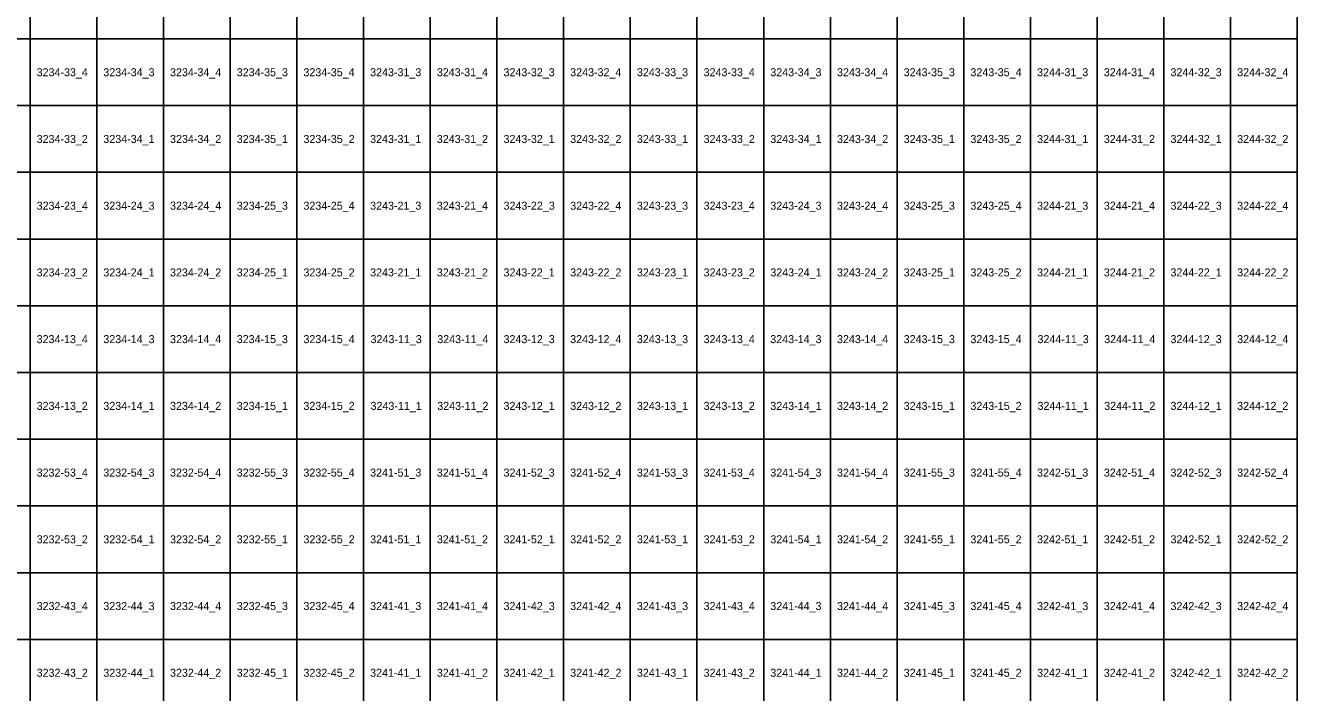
# Model space of a CAD drawing. Extents: x 312500 to 765000, y 172500 to 440000.
# Drawn here: x 437325 to 484827, y 265505 to 290507 of the extents above; entities that cross this region are included whole.
import ezdxf

# ---------------------------------------------------------------- set-up
doc = ezdxf.new("R2010")
doc.units = 0
doc.layers.add('Topo5_ramis_TKS2025', color=7, linetype='Continuous')
doc.layers.add('Topo5_ramis_TKS2025_Nr', color=7, linetype='Continuous')

msp = doc.modelspace()

# ---------------------------------------------------------------- linework, layer by layer
at = {"layer": 'Topo5_ramis_TKS2025'}
for points in [[(435000, 290000), (435000, 292500), (437500, 292500), (437500, 290000), (435000, 290000)], [(437500, 290000), (437500, 292500), (440000, 292500), (440000, 290000), (437500, 290000)], [(440000, 290000), (440000, 292500), (442500, 292500), (442500, 290000), (440000, 290000)], [(442500, 290000), (442500, 292500), (445000, 292500), (445000, 290000), (442500, 290000)], [(445000, 290000), (445000, 292500), (447500, 292500), (447500, 290000), (445000, 290000)], [(447500, 290000), (447500, 292500), (450000, 292500), (450000, 290000), (447500, 290000)], [(450000, 290000), (450000, 292500), (452500, 292500), (452500, 290000), (450000, 290000)], [(452500, 290000), (452500, 292500), (455000, 292500), (455000, 290000), (452500, 290000)], [(455000, 290000), (455000, 292500), (457500, 292500), (457500, 290000), (455000, 290000)], [(457500, 290000), (457500, 292500), (460000, 292500), (460000, 290000), (457500, 290000)], [(460000, 290000), (460000, 292500), (462500, 292500), (462500, 290000), (460000, 290000)], [(462500, 290000), (462500, 292500), (465000, 292500), (465000, 290000), (462500, 290000)], [(465000, 290000), (465000, 292500), (467500, 292500), (467500, 290000), (465000, 290000)], [(467500, 290000), (467500, 292500), (470000, 292500), (470000, 290000), (467500, 290000)], [(470000, 290000), (470000, 292500), (472500, 292500), (472500, 290000), (470000, 290000)], [(472500, 290000), (472500, 292500), (475000, 292500), (475000, 290000), (472500, 290000)], [(475000, 290000), (475000, 292500), (477500, 292500), (477500, 290000), (475000, 290000)], [(477500, 290000), (477500, 292500), (480000, 292500), (480000, 290000), (477500, 290000)], [(480000, 290000), (480000, 292500), (482500, 292500), (482500, 290000), (480000, 290000)], [(482500, 290000), (482500, 292500), (485000, 292500), (485000, 290000), (482500, 290000)], [(435000, 287500), (435000, 290000), (437500, 290000), (437500, 287500), (435000, 287500)], [(437500, 287500), (437500, 290000), (440000, 290000), (440000, 287500), (437500, 287500)], [(440000, 287500), (440000, 290000), (442500, 290000), (442500, 287500), (440000, 287500)], [(442500, 287500), (442500, 290000), (445000, 290000), (445000, 287500), (442500, 287500)], [(445000, 287500), (445000, 290000), (447500, 290000), (447500, 287500), (445000, 287500)], [(447500, 287500), (447500, 290000), (450000, 290000), (450000, 287500), (447500, 287500)], [(450000, 287500), (450000, 290000), (452500, 290000), (452500, 287500), (450000, 287500)], [(452500, 287500), (452500, 290000), (455000, 290000), (455000, 287500), (452500, 287500)], [(455000, 287500), (455000, 290000), (457500, 290000), (457500, 287500), (455000, 287500)], [(457500, 287500), (457500, 290000), (460000, 290000), (460000, 287500), (457500, 287500)], [(460000, 287500), (460000, 290000), (462500, 290000), (462500, 287500), (460000, 287500)], [(462500, 287500), (462500, 290000), (465000, 290000), (465000, 287500), (462500, 287500)], [(465000, 287500), (465000, 290000), (467500, 290000), (467500, 287500), (465000, 287500)], [(467500, 287500), (467500, 290000), (470000, 290000), (470000, 287500), (467500, 287500)], [(470000, 287500), (470000, 290000), (472500, 290000), (472500, 287500), (470000, 287500)], [(472500, 287500), (472500, 290000), (475000, 290000), (475000, 287500), (472500, 287500)], [(475000, 287500), (475000, 290000), (477500, 290000), (477500, 287500), (475000, 287500)], [(477500, 287500), (477500, 290000), (480000, 290000), (480000, 287500), (477500, 287500)], [(480000, 287500), (480000, 290000), (482500, 290000), (482500, 287500), (480000, 287500)], [(482500, 287500), (482500, 290000), (485000, 290000), (485000, 287500), (482500, 287500)], [(435000, 285000), (435000, 287500), (437500, 287500), (437500, 285000), (435000, 285000)], [(437500, 285000), (437500, 287500), (440000, 287500), (440000, 285000), (437500, 285000)], [(440000, 285000), (440000, 287500), (442500, 287500), (442500, 285000), (440000, 285000)], [(442500, 285000), (442500, 287500), (445000, 287500), (445000, 285000), (442500, 285000)], [(445000, 285000), (445000, 287500), (447500, 287500), (447500, 285000), (445000, 285000)], [(447500, 285000), (447500, 287500), (450000, 287500), (450000, 285000), (447500, 285000)], [(450000, 285000), (450000, 287500), (452500, 287500), (452500, 285000), (450000, 285000)], [(452500, 285000), (452500, 287500), (455000, 287500), (455000, 285000), (452500, 285000)], [(455000, 285000), (455000, 287500), (457500, 287500), (457500, 285000), (455000, 285000)], [(457500, 285000), (457500, 287500), (460000, 287500), (460000, 285000), (457500, 285000)], [(460000, 285000), (460000, 287500), (462500, 287500), (462500, 285000), (460000, 285000)], [(462500, 285000), (462500, 287500), (465000, 287500), (465000, 285000), (462500, 285000)], [(465000, 285000), (465000, 287500), (467500, 287500), (467500, 285000), (465000, 285000)], [(467500, 285000), (467500, 287500), (470000, 287500), (470000, 285000), (467500, 285000)], [(470000, 285000), (470000, 287500), (472500, 287500), (472500, 285000), (470000, 285000)], [(472500, 285000), (472500, 287500), (475000, 287500), (475000, 285000), (472500, 285000)], [(475000, 285000), (475000, 287500), (477500, 287500), (477500, 285000), (475000, 285000)], [(477500, 285000), (477500, 287500), (480000, 287500), (480000, 285000), (477500, 285000)], [(480000, 285000), (480000, 287500), (482500, 287500), (482500, 285000), (480000, 285000)], [(482500, 285000), (482500, 287500), (485000, 287500), (485000, 285000), (482500, 285000)], [(435000, 282500), (435000, 285000), (437500, 285000), (437500, 282500), (435000, 282500)], [(437500, 282500), (437500, 285000), (440000, 285000), (440000, 282500), (437500, 282500)], [(440000, 282500), (440000, 285000), (442500, 285000), (442500, 282500), (440000, 282500)], [(442500, 282500), (442500, 285000), (445000, 285000), (445000, 282500), (442500, 282500)], [(445000, 282500), (445000, 285000), (447500, 285000), (447500, 282500), (445000, 282500)], [(447500, 282500), (447500, 285000), (450000, 285000), (450000, 282500), (447500, 282500)], [(450000, 282500), (450000, 285000), (452500, 285000), (452500, 282500), (450000, 282500)], [(452500, 282500), (452500, 285000), (455000, 285000), (455000, 282500), (452500, 282500)], [(455000, 282500), (455000, 285000), (457500, 285000), (457500, 282500), (455000, 282500)], [(457500, 282500), (457500, 285000), (460000, 285000), (460000, 282500), (457500, 282500)], [(460000, 282500), (460000, 285000), (462500, 285000), (462500, 282500), (460000, 282500)], [(462500, 282500), (462500, 285000), (465000, 285000), (465000, 282500), (462500, 282500)], [(465000, 282500), (465000, 285000), (467500, 285000), (467500, 282500), (465000, 282500)], [(467500, 282500), (467500, 285000), (470000, 285000), (470000, 282500), (467500, 282500)], [(470000, 282500), (470000, 285000), (472500, 285000), (472500, 282500), (470000, 282500)], [(472500, 282500), (472500, 285000), (475000, 285000), (475000, 282500), (472500, 282500)], [(475000, 282500), (475000, 285000), (477500, 285000), (477500, 282500), (475000, 282500)], [(477500, 282500), (477500, 285000), (480000, 285000), (480000, 282500), (477500, 282500)], [(480000, 282500), (480000, 285000), (482500, 285000), (482500, 282500), (480000, 282500)], [(482500, 282500), (482500, 285000), (485000, 285000), (485000, 282500), (482500, 282500)], [(435000, 280000), (435000, 282500), (437500, 282500), (437500, 280000), (435000, 280000)], [(437500, 280000), (437500, 282500), (440000, 282500), (440000, 280000), (437500, 280000)], [(440000, 280000), (440000, 282500), (442500, 282500), (442500, 280000), (440000, 280000)], [(442500, 280000), (442500, 282500), (445000, 282500), (445000, 280000), (442500, 280000)], [(445000, 280000), (445000, 282500), (447500, 282500), (447500, 280000), (445000, 280000)], [(447500, 280000), (447500, 282500), (450000, 282500), (450000, 280000), (447500, 280000)], [(450000, 280000), (450000, 282500), (452500, 282500), (452500, 280000), (450000, 280000)], [(452500, 280000), (452500, 282500), (455000, 282500), (455000, 280000), (452500, 280000)], [(455000, 280000), (455000, 282500), (457500, 282500), (457500, 280000), (455000, 280000)], [(457500, 280000), (457500, 282500), (460000, 282500), (460000, 280000), (457500, 280000)], [(460000, 280000), (460000, 282500), (462500, 282500), (462500, 280000), (460000, 280000)], [(462500, 280000), (462500, 282500), (465000, 282500), (465000, 280000), (462500, 280000)], [(465000, 280000), (465000, 282500), (467500, 282500), (467500, 280000), (465000, 280000)], [(467500, 280000), (467500, 282500), (470000, 282500), (470000, 280000), (467500, 280000)], [(470000, 280000), (470000, 282500), (472500, 282500), (472500, 280000), (470000, 280000)], [(472500, 280000), (472500, 282500), (475000, 282500), (475000, 280000), (472500, 280000)], [(475000, 280000), (475000, 282500), (477500, 282500), (477500, 280000), (475000, 280000)], [(477500, 280000), (477500, 282500), (480000, 282500), (480000, 280000), (477500, 280000)], [(480000, 280000), (480000, 282500), (482500, 282500), (482500, 280000), (480000, 280000)], [(482500, 280000), (482500, 282500), (485000, 282500), (485000, 280000), (482500, 280000)], [(435000, 277500), (435000, 280000), (437500, 280000), (437500, 277500), (435000, 277500)], [(437500, 277500), (437500, 280000), (440000, 280000), (440000, 277500), (437500, 277500)], [(440000, 277500), (440000, 280000), (442500, 280000), (442500, 277500), (440000, 277500)], [(442500, 277500), (442500, 280000), (445000, 280000), (445000, 277500), (442500, 277500)], [(445000, 277500), (445000, 280000), (447500, 280000), (447500, 277500), (445000, 277500)], [(447500, 277500), (447500, 280000), (450000, 280000), (450000, 277500), (447500, 277500)], [(450000, 277500), (450000, 280000), (452500, 280000), (452500, 277500), (450000, 277500)], [(452500, 277500), (452500, 280000), (455000, 280000), (455000, 277500), (452500, 277500)], [(455000, 277500), (455000, 280000), (457500, 280000), (457500, 277500), (455000, 277500)], [(457500, 277500), (457500, 280000), (460000, 280000), (460000, 277500), (457500, 277500)], [(460000, 277500), (460000, 280000), (462500, 280000), (462500, 277500), (460000, 277500)], [(462500, 277500), (462500, 280000), (465000, 280000), (465000, 277500), (462500, 277500)], [(465000, 277500), (465000, 280000), (467500, 280000), (467500, 277500), (465000, 277500)], [(467500, 277500), (467500, 280000), (470000, 280000), (470000, 277500), (467500, 277500)], [(470000, 277500), (470000, 280000), (472500, 280000), (472500, 277500), (470000, 277500)], [(472500, 277500), (472500, 280000), (475000, 280000), (475000, 277500), (472500, 277500)], [(475000, 277500), (475000, 280000), (477500, 280000), (477500, 277500), (475000, 277500)], [(477500, 277500), (477500, 280000), (480000, 280000), (480000, 277500), (477500, 277500)], [(480000, 277500), (480000, 280000), (482500, 280000), (482500, 277500), (480000, 277500)], [(482500, 277500), (482500, 280000), (485000, 280000), (485000, 277500), (482500, 277500)], [(435000, 275000), (435000, 277500), (437500, 277500), (437500, 275000), (435000, 275000)], [(437500, 275000), (437500, 277500), (440000, 277500), (440000, 275000), (437500, 275000)], [(440000, 275000), (440000, 277500), (442500, 277500), (442500, 275000), (440000, 275000)], [(442500, 275000), (442500, 277500), (445000, 277500), (445000, 275000), (442500, 275000)], [(445000, 275000), (445000, 277500), (447500, 277500), (447500, 275000), (445000, 275000)], [(447500, 275000), (447500, 277500), (450000, 277500), (450000, 275000), (447500, 275000)], [(450000, 275000), (450000, 277500), (452500, 277500), (452500, 275000), (450000, 275000)], [(452500, 275000), (452500, 277500), (455000, 277500), (455000, 275000), (452500, 275000)], [(455000, 275000), (455000, 277500), (457500, 277500), (457500, 275000), (455000, 275000)], [(457500, 275000), (457500, 277500), (460000, 277500), (460000, 275000), (457500, 275000)], [(460000, 275000), (460000, 277500), (462500, 277500), (462500, 275000), (460000, 275000)], [(462500, 275000), (462500, 277500), (465000, 277500), (465000, 275000), (462500, 275000)], [(465000, 275000), (465000, 277500), (467500, 277500), (467500, 275000), (465000, 275000)], [(467500, 275000), (467500, 277500), (470000, 277500), (470000, 275000), (467500, 275000)], [(470000, 275000), (470000, 277500), (472500, 277500), (472500, 275000), (470000, 275000)], [(472500, 275000), (472500, 277500), (475000, 277500), (475000, 275000), (472500, 275000)], [(475000, 275000), (475000, 277500), (477500, 277500), (477500, 275000), (475000, 275000)], [(477500, 275000), (477500, 277500), (480000, 277500), (480000, 275000), (477500, 275000)], [(480000, 275000), (480000, 277500), (482500, 277500), (482500, 275000), (480000, 275000)], [(482500, 275000), (482500, 277500), (485000, 277500), (485000, 275000), (482500, 275000)], [(435000, 272500), (435000, 275000), (437500, 275000), (437500, 272500), (435000, 272500)], [(437500, 272500), (437500, 275000), (440000, 275000), (440000, 272500), (437500, 272500)], [(440000, 272500), (440000, 275000), (442500, 275000), (442500, 272500), (440000, 272500)], [(442500, 272500), (442500, 275000), (445000, 275000), (445000, 272500), (442500, 272500)], [(445000, 272500), (445000, 275000), (447500, 275000), (447500, 272500), (445000, 272500)], [(447500, 272500), (447500, 275000), (450000, 275000), (450000, 272500), (447500, 272500)], [(450000, 272500), (450000, 275000), (452500, 275000), (452500, 272500), (450000, 272500)], [(452500, 272500), (452500, 275000), (455000, 275000), (455000, 272500), (452500, 272500)], [(455000, 272500), (455000, 275000), (457500, 275000), (457500, 272500), (455000, 272500)], [(457500, 272500), (457500, 275000), (460000, 275000), (460000, 272500), (457500, 272500)], [(460000, 272500), (460000, 275000), (462500, 275000), (462500, 272500), (460000, 272500)], [(462500, 272500), (462500, 275000), (465000, 275000), (465000, 272500), (462500, 272500)], [(465000, 272500), (465000, 275000), (467500, 275000), (467500, 272500), (465000, 272500)], [(467500, 272500), (467500, 275000), (470000, 275000), (470000, 272500), (467500, 272500)], [(470000, 272500), (470000, 275000), (472500, 275000), (472500, 272500), (470000, 272500)], [(472500, 272500), (472500, 275000), (475000, 275000), (475000, 272500), (472500, 272500)], [(475000, 272500), (475000, 275000), (477500, 275000), (477500, 272500), (475000, 272500)], [(477500, 272500), (477500, 275000), (480000, 275000), (480000, 272500), (477500, 272500)], [(480000, 272500), (480000, 275000), (482500, 275000), (482500, 272500), (480000, 272500)], [(482500, 272500), (482500, 275000), (485000, 275000), (485000, 272500), (482500, 272500)], [(435000, 270000), (435000, 272500), (437500, 272500), (437500, 270000), (435000, 270000)], [(437500, 270000), (437500, 272500), (440000, 272500), (440000, 270000), (437500, 270000)], [(440000, 270000), (440000, 272500), (442500, 272500), (442500, 270000), (440000, 270000)], [(442500, 270000), (442500, 272500), (445000, 272500), (445000, 270000), (442500, 270000)], [(445000, 270000), (445000, 272500), (447500, 272500), (447500, 270000), (445000, 270000)], [(447500, 270000), (447500, 272500), (450000, 272500), (450000, 270000), (447500, 270000)], [(450000, 270000), (450000, 272500), (452500, 272500), (452500, 270000), (450000, 270000)], [(452500, 270000), (452500, 272500), (455000, 272500), (455000, 270000), (452500, 270000)], [(455000, 270000), (455000, 272500), (457500, 272500), (457500, 270000), (455000, 270000)], [(457500, 270000), (457500, 272500), (460000, 272500), (460000, 270000), (457500, 270000)], [(460000, 270000), (460000, 272500), (462500, 272500), (462500, 270000), (460000, 270000)], [(462500, 270000), (462500, 272500), (465000, 272500), (465000, 270000), (462500, 270000)], [(465000, 270000), (465000, 272500), (467500, 272500), (467500, 270000), (465000, 270000)], [(467500, 270000), (467500, 272500), (470000, 272500), (470000, 270000), (467500, 270000)], [(470000, 270000), (470000, 272500), (472500, 272500), (472500, 270000), (470000, 270000)], [(472500, 270000), (472500, 272500), (475000, 272500), (475000, 270000), (472500, 270000)], [(475000, 270000), (475000, 272500), (477500, 272500), (477500, 270000), (475000, 270000)], [(477500, 270000), (477500, 272500), (480000, 272500), (480000, 270000), (477500, 270000)], [(480000, 270000), (480000, 272500), (482500, 272500), (482500, 270000), (480000, 270000)], [(482500, 270000), (482500, 272500), (485000, 272500), (485000, 270000), (482500, 270000)], [(435000, 267500), (435000, 270000), (437500, 270000), (437500, 267500), (435000, 267500)], [(437500, 267500), (437500, 270000), (440000, 270000), (440000, 267500), (437500, 267500)], [(440000, 267500), (440000, 270000), (442500, 270000), (442500, 267500), (440000, 267500)], [(442500, 267500), (442500, 270000), (445000, 270000), (445000, 267500), (442500, 267500)], [(445000, 267500), (445000, 270000), (447500, 270000), (447500, 267500), (445000, 267500)], [(447500, 267500), (447500, 270000), (450000, 270000), (450000, 267500), (447500, 267500)], [(450000, 267500), (450000, 270000), (452500, 270000), (452500, 267500), (450000, 267500)], [(452500, 267500), (452500, 270000), (455000, 270000), (455000, 267500), (452500, 267500)], [(455000, 267500), (455000, 270000), (457500, 270000), (457500, 267500), (455000, 267500)], [(457500, 267500), (457500, 270000), (460000, 270000), (460000, 267500), (457500, 267500)], [(460000, 267500), (460000, 270000), (462500, 270000), (462500, 267500), (460000, 267500)], [(462500, 267500), (462500, 270000), (465000, 270000), (465000, 267500), (462500, 267500)], [(465000, 267500), (465000, 270000), (467500, 270000), (467500, 267500), (465000, 267500)], [(467500, 267500), (467500, 270000), (470000, 270000), (470000, 267500), (467500, 267500)], [(470000, 267500), (470000, 270000), (472500, 270000), (472500, 267500), (470000, 267500)], [(472500, 267500), (472500, 270000), (475000, 270000), (475000, 267500), (472500, 267500)], [(475000, 267500), (475000, 270000), (477500, 270000), (477500, 267500), (475000, 267500)], [(477500, 267500), (477500, 270000), (480000, 270000), (480000, 267500), (477500, 267500)], [(480000, 267500), (480000, 270000), (482500, 270000), (482500, 267500), (480000, 267500)], [(482500, 267500), (482500, 270000), (485000, 270000), (485000, 267500), (482500, 267500)], [(435000, 265000), (435000, 267500), (437500, 267500), (437500, 265000), (435000, 265000)], [(437500, 265000), (437500, 267500), (440000, 267500), (440000, 265000), (437500, 265000)], [(440000, 265000), (440000, 267500), (442500, 267500), (442500, 265000), (440000, 265000)], [(442500, 265000), (442500, 267500), (445000, 267500), (445000, 265000), (442500, 265000)], [(445000, 265000), (445000, 267500), (447500, 267500), (447500, 265000), (445000, 265000)], [(447500, 265000), (447500, 267500), (450000, 267500), (450000, 265000), (447500, 265000)], [(450000, 265000), (450000, 267500), (452500, 267500), (452500, 265000), (450000, 265000)], [(452500, 265000), (452500, 267500), (455000, 267500), (455000, 265000), (452500, 265000)], [(455000, 265000), (455000, 267500), (457500, 267500), (457500, 265000), (455000, 265000)], [(457500, 265000), (457500, 267500), (460000, 267500), (460000, 265000), (457500, 265000)], [(460000, 265000), (460000, 267500), (462500, 267500), (462500, 265000), (460000, 265000)], [(462500, 265000), (462500, 267500), (465000, 267500), (465000, 265000), (462500, 265000)], [(465000, 265000), (465000, 267500), (467500, 267500), (467500, 265000), (465000, 265000)], [(467500, 265000), (467500, 267500), (470000, 267500), (470000, 265000), (467500, 265000)], [(470000, 265000), (470000, 267500), (472500, 267500), (472500, 265000), (470000, 265000)], [(472500, 265000), (472500, 267500), (475000, 267500), (475000, 265000), (472500, 265000)], [(475000, 265000), (475000, 267500), (477500, 267500), (477500, 265000), (475000, 265000)], [(477500, 265000), (477500, 267500), (480000, 267500), (480000, 265000), (477500, 265000)], [(480000, 265000), (480000, 267500), (482500, 267500), (482500, 265000), (480000, 265000)], [(482500, 265000), (482500, 267500), (485000, 267500), (485000, 265000), (482500, 265000)]]:
    msp.add_lwpolyline(points, dxfattribs=at)

# ---------------------------------------------------------------- texts
at = {"layer": 'Topo5_ramis_TKS2025_Nr'}
for s, p in [('3234-33_4', (437748, 288600)), ('3234-34_3', (440248, 288600)), ('3234-34_4', (442748, 288600)), ('3234-35_3', (445248, 288600)), ('3234-35_4', (447748, 288600)), ('3243-31_3', (450248, 288600)), ('3243-31_4', (452748, 288600)), ('3243-32_3', (455248, 288600)), ('3243-32_4', (457748, 288600)), ('3243-33_3', (460248, 288600)), ('3243-33_4', (462748, 288600)), ('3243-34_3', (465248, 288600)), ('3243-34_4', (467748, 288600)), ('3243-35_3', (470248, 288600)), ('3243-35_4', (472748, 288600)), ('3244-31_3', (475248, 288600)), ('3244-31_4', (477748, 288600)), ('3244-32_3', (480248, 288600)), ('3244-32_4', (482748, 288600)), ('3234-33_2', (437748, 286100)), ('3234-34_1', (440248, 286100)), ('3234-34_2', (442748, 286100)), ('3234-35_1', (445248, 286100)), ('3234-35_2', (447748, 286100)), ('3243-31_1', (450248, 286100)), ('3243-31_2', (452748, 286100)), ('3243-32_1', (455248, 286100)), ('3243-32_2', (457748, 286100)), ('3243-33_1', (460248, 286100)), ('3243-33_2', (462748, 286100)), ('3243-34_1', (465248, 286100)), ('3243-34_2', (467748, 286100)), ('3243-35_1', (470248, 286100)), ('3243-35_2', (472748, 286100)), ('3244-31_1', (475248, 286100)), ('3244-31_2', (477748, 286100)), ('3244-32_1', (480248, 286100)), ('3244-32_2', (482748, 286100)), ('3234-23_4', (437748, 283600)), ('3234-24_3', (440248, 283600)), ('3234-24_4', (442748, 283600)), ('3234-25_3', (445248, 283600)), ('3234-25_4', (447748, 283600)), ('3243-21_3', (450248, 283600)), ('3243-21_4', (452748, 283600)), ('3243-22_3', (455248, 283600)), ('3243-22_4', (457748, 283600)), ('3243-23_3', (460248, 283600)), ('3243-23_4', (462748, 283600)), ('3243-24_3', (465248, 283600)), ('3243-24_4', (467748, 283600)), ('3243-25_3', (470248, 283600)), ('3243-25_4', (472748, 283600)), ('3244-21_3', (475248, 283600)), ('3244-21_4', (477748, 283600)), ('3244-22_3', (480248, 283600)), ('3244-22_4', (482748, 283600)), ('3234-23_2', (437748, 281100)), ('3234-24_1', (440248, 281100)), ('3234-24_2', (442748, 281100)), ('3234-25_1', (445248, 281100)), ('3234-25_2', (447748, 281100)), ('3243-21_1', (450248, 281100)), ('3243-21_2', (452748, 281100)), ('3243-22_1', (455248, 281100)), ('3243-22_2', (457748, 281100)), ('3243-23_1', (460248, 281100)), ('3243-23_2', (462748, 281100)), ('3243-24_1', (465248, 281100)), ('3243-24_2', (467748, 281100)), ('3243-25_1', (470248, 281100)), ('3243-25_2', (472748, 281100)), ('3244-21_1', (475248, 281100)), ('3244-21_2', (477748, 281100)), ('3244-22_1', (480248, 281100)), ('3244-22_2', (482748, 281100)), ('3234-13_4', (437748, 278600)), ('3234-14_3', (440248, 278600)), ('3234-14_4', (442748, 278600)), ('3234-15_3', (445248, 278600)), ('3234-15_4', (447748, 278600)), ('3243-11_3', (450264, 278600)), ('3243-11_4', (452764, 278600)), ('3243-12_3', (455248, 278600)), ('3243-12_4', (457748, 278600)), ('3243-13_3', (460248, 278600)), ('3243-13_4', (462748, 278600)), ('3243-14_3', (465248, 278600)), ('3243-14_4', (467748, 278600)), ('3243-15_3', (470248, 278600)), ('3243-15_4', (472748, 278600)), ('3244-11_3', (475264, 278600)), ('3244-11_4', (477764, 278600)), ('3244-12_3', (480248, 278600)), ('3244-12_4', (482748, 278600)), ('3234-13_2', (437748, 276100)), ('3234-14_1', (440248, 276100)), ('3234-14_2', (442748, 276100)), ('3234-15_1', (445248, 276100)), ('3234-15_2', (447748, 276100)), ('3243-11_1', (450264, 276100)), ('3243-11_2', (452764, 276100)), ('3243-12_1', (455248, 276100)), ('3243-12_2', (457748, 276100)), ('3243-13_1', (460248, 276100)), ('3243-13_2', (462748, 276100)), ('3243-14_1', (465248, 276100)), ('3243-14_2', (467748, 276100)), ('3243-15_1', (470248, 276100)), ('3243-15_2', (472748, 276100)), ('3244-11_1', (475264, 276100)), ('3244-11_2', (477764, 276100)), ('3244-12_1', (480248, 276100)), ('3244-12_2', (482748, 276100)), ('3232-53_4', (437748, 273600)), ('3232-54_3', (440248, 273600)), ('3232-54_4', (442748, 273600)), ('3232-55_3', (445248, 273600)), ('3232-55_4', (447748, 273600)), ('3241-51_3', (450248, 273600)), ('3241-51_4', (452748, 273600)), ('3241-52_3', (455248, 273600)), ('3241-52_4', (457748, 273600)), ('3241-53_3', (460248, 273600)), ('3241-53_4', (462748, 273600)), ('3241-54_3', (465248, 273600)), ('3241-54_4', (467748, 273600)), ('3241-55_3', (470248, 273600)), ('3241-55_4', (472748, 273600)), ('3242-51_3', (475248, 273600)), ('3242-51_4', (477748, 273600)), ('3242-52_3', (480248, 273600)), ('3242-52_4', (482748, 273600)), ('3232-53_2', (437748, 271100)), ('3232-54_1', (440248, 271100)), ('3232-54_2', (442748, 271100)), ('3232-55_1', (445248, 271100)), ('3232-55_2', (447748, 271100)), ('3241-51_1', (450248, 271100)), ('3241-51_2', (452748, 271100)), ('3241-52_1', (455248, 271100)), ('3241-52_2', (457748, 271100)), ('3241-53_1', (460248, 271100)), ('3241-53_2', (462748, 271100)), ('3241-54_1', (465248, 271100)), ('3241-54_2', (467748, 271100)), ('3241-55_1', (470248, 271100)), ('3241-55_2', (472748, 271100)), ('3242-51_1', (475248, 271100)), ('3242-51_2', (477748, 271100)), ('3242-52_1', (480248, 271100)), ('3242-52_2', (482748, 271100)), ('3232-43_4', (437748, 268600)), ('3232-44_3', (440248, 268600)), ('3232-44_4', (442748, 268600)), ('3232-45_3', (445248, 268600)), ('3232-45_4', (447748, 268600)), ('3241-41_3', (450248, 268600)), ('3241-41_4', (452748, 268600)), ('3241-42_3', (455248, 268600)), ('3241-42_4', (457748, 268600)), ('3241-43_3', (460248, 268600)), ('3241-43_4', (462748, 268600)), ('3241-44_3', (465248, 268600)), ('3241-44_4', (467748, 268600)), ('3241-45_3', (470248, 268600)), ('3241-45_4', (472748, 268600)), ('3242-41_3', (475248, 268600)), ('3242-41_4', (477748, 268600)), ('3242-42_3', (480248, 268600)), ('3242-42_4', (482748, 268600)), ('3232-43_2', (437748, 266100)), ('3232-44_1', (440248, 266100)), ('3232-44_2', (442748, 266100)), ('3232-45_1', (445248, 266100)), ('3232-45_2', (447748, 266100)), ('3241-41_1', (450248, 266100)), ('3241-41_2', (452748, 266100)), ('3241-42_1', (455248, 266100)), ('3241-42_2', (457748, 266100)), ('3241-43_1', (460248, 266100)), ('3241-43_2', (462748, 266100)), ('3241-44_1', (465248, 266100)), ('3241-44_2', (467748, 266100)), ('3241-45_1', (470248, 266100)), ('3241-45_2', (472748, 266100)), ('3242-41_1', (475248, 266100)), ('3242-41_2', (477748, 266100)), ('3242-42_1', (480248, 266100)), ('3242-42_2', (482748, 266100))]:
    msp.add_text(s, height=300, dxfattribs=at).set_placement(p)

doc.saveas('drawing.dxf')
